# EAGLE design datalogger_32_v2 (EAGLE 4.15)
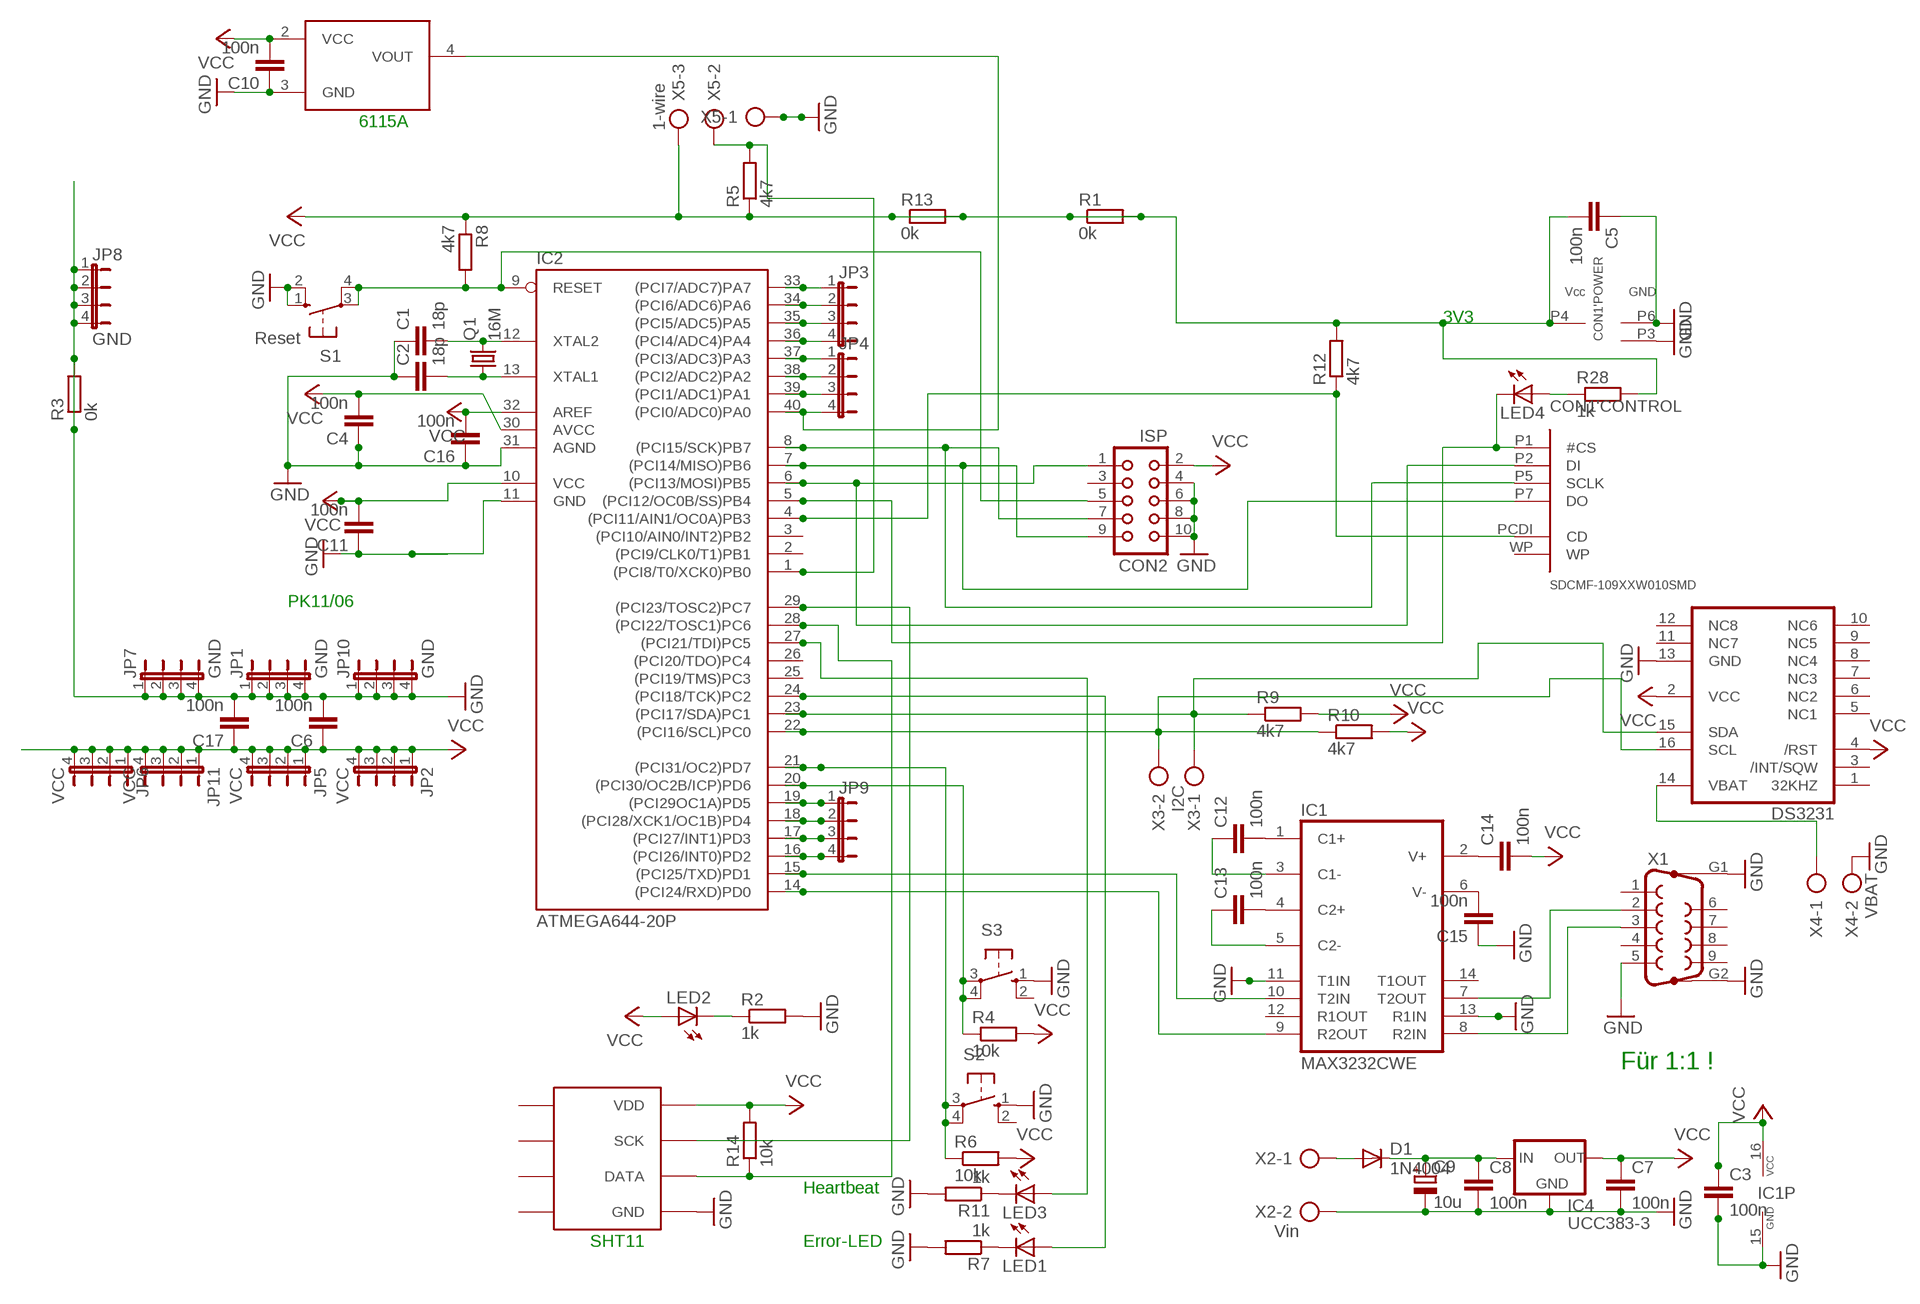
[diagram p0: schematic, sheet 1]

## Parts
C1  18p  C-EUC1206  [C1206]
C2  18p  C-EUC1206  [C1206]
C3  100n  C-EUC1206  [C1206]
C4  100n  C-EUC1206  [C1206]
C5  100n  C-EUC1206  [C1206]
C6  100n  C-EUC1206  [C1206]
C7  100n  C-EUC1206  [C1206]
C8  100n  C-EUC1206  [C1206]
C9  10u  CPOL-EU153CLV-0505  [153CLV-0505]
C10  100n  C-EUC1206  [C1206]
C11  100n  C-EUC1206  [C1206]
C12  100n  C-EUC1206  [C1206]
C13  100n  C-EUC1206  [C1206]
C14  100n  C-EUC1206  [C1206]
C15  100n  C-EUC1206  [C1206]
C16  100n  C-EUC1206  [C1206]
C17  100n  C-EUC1206  [C1206]
CON1  SDCMF-109XXW010SMD  [SDCMF-109XXW010]
CON2  ISP  CON10  [CON10]
D1  1N4004  [DO41-10]
DS3231  DS3231  [SO16L]
IC1  MAX3232CWE  [SO16L]
IC2  ATMEGA644-20P  [DIL40]
IC4  UCC383-3  78XXS  [78XXS]
JP1  GND  JP4E  [JP4]
JP2  VCC  JP4E  [JP4]
JP3  JP4E  [JP4]
JP4  JP4E  [JP4]
JP5  VCC  JP4E  [JP4]
JP6  VCC  JP4E  [JP4]
JP7  GND  JP4E  [JP4]
JP8  GND  JP4E  [JP4]
JP9  JP4E  [JP4]
JP10  GND  JP4E  [JP4]
JP11  VCC  JP4E  [JP4]
LED1  LEDSMT1206  [1206]
LED2  LEDSMT1206  [1206]
LED3  LEDSMT1206  [1206]
LED4  LEDSMT1206  [1206]
Q1  16M  CRYTALHC49U-V  [HC49U-V]
R1  0k  R-EU_R1206  [R1206]
R2  1k  R-EU_R1206  [R1206]
R3  0k  R-EU_R1206  [R1206]
R4  10k  R-EU_M1206  [M1206]
R5  4k7  R-EU_R1206  [R1206]
R6  10k  R-EU_M1206  [M1206]
R7  1k  R-EU_R1206  [R1206]
R8  4k7  R-EU_R1206  [R1206]
R9  4k7  R-EU_M1206  [M1206]
R10  4k7  R-EU_R1206  [R1206]
R11  1k  R-EU_R1206  [R1206]
R12  4k7  R-EU_R1206  [R1206]
R13  0k  R-EU_R1206  [R1206]
R14  10k  R-EU_R1206  [R1206]
R28  1k  R-EU_R1206  [R1206]
S1  Reset  10-XX  [B3F-10XX]
S2  10-XX  [B3F-10XX]
S3  10-XX  [B3F-10XX]
SHT1  SHT11  [SHT11]
U$1  MPXHZ6115A  [SO08W]
X1  F09HP  [F09HP]
X2  Vin  AK500/2  [AK500/2]
X3  I2C  AK500/2  [AK500/2]
X4  VBAT  AK500/2  [AK500/2]
X5  1-wire  AK500/3  [AK500/3]

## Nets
GND: C1.1 C2.1 C3.2 C4.1 C5.1 C6.2 C7.2 C8.2 C9.- C10.1 C11.1 C15.1 C16.1 C17.2 CON1.P3('POWER:GND) CON1.P6('POWER:GND) CON2.4 CON2.6 CON2.8 CON2.10 DS3231.13(GND) IC1.11(T1IN) IC1.13(R1IN) IC1.15(GND) IC2.11(GND) IC2.31(AGND) IC4.GND JP1.1 JP1.2 JP1.3 JP1.4 JP7.1 JP7.2 JP7.3 JP7.4 JP8.1 JP8.2 JP8.3 JP8.4 JP10.1 JP10.2 JP10.3 JP10.4 R2.2 R3.1 R3.2 R7.2 R11.2 S1.1(S) S1.2(S1) S2.1(S) S3.1(S) SHT1.GND U$1.3(GND) X1.5 X1.G1 X1.G2 X2.2 X4.2 X5.1
N$1: C1.2 IC2.12(XTAL2) Q1.2
N$2: C2.2 IC2.13(XTAL1) Q1.1
N$3: CON1.P1('CONTROL:#CS) IC2.5((PCI12/OC0B/SS)PB4) LED4.C
N$4: CON1.P2('CONTROL:DI) CON2.1 IC2.6((PCI13/MOSI)PB5)
N$5: IC2.17((PCI27/INT1)PD3) JP9.3
N$6: IC1.10(T2IN) IC2.15((PCI25/TXD)PD1)
N$7: IC2.18((PCI28/XCK1/OC1B)PD4) JP9.2
N$8: IC2.16((PCI26/INT0)PD2) JP9.4
N$9: CON1.P7('CONTROL:DO) CON2.9 IC2.7((PCI14/MISO)PB6)
N$10: IC2.19((PCI29OC1A)PD5) JP9.1
N$11: IC2.40((PCI0/ADC0)PA0) JP4.4 U$1.4(VOUT)
N$12: IC2.39((PCI1/ADC1)PA1) JP4.3
N$13: IC2.38((PCI2/ADC2)PA2) JP4.2
N$14: IC2.37((PCI3/ADC3)PA3) JP4.1
N$15: DS3231.15(SDA) IC2.23((PCI17/SDA)PC1) R9.1 X3.1
N$17: C8.1 C9.+ D1.C IC4.IN
N$18: IC1.9(R2OUT) IC2.14((PCI24/RXD)PD0)
N$19: IC2.33((PCI7/ADC7)PA7) JP3.1
N$20: LED2.C R2.1
N$24: DS3231.14(VBAT) X4.1
N$25: D1.A X2.1
N$27: IC2.20((PCI30/OC2B/ICP)PD6) R4.1 S3.3(P) S3.4(P1)
N$28: IC2.21((PCI31/OC2)PD7) R6.1 S2.3(P) S2.4(P1)
N$29: CON1.P5('CONTROL:SCLK) CON2.7 IC2.8((PCI15/SCK)PB7)
N$30: LED1.C R7.1
N$31: DS3231.16(SCL) IC2.22((PCI16/SCL)PC0) R10.1 X3.2
N$32: IC1.8(R2IN) X1.3
N$33: IC1.7(T2OUT) X1.2
N$34: IC2.29((PCI23/TOSC2)PC7) SHT1.SCK
N$35: C12.2 IC1.1(C1+)
N$36: C13.2 IC1.4(C2+)
N$37: LED3.C R11.1
N$39: C14.1 IC1.2(V+)
N$40: IC2.34((PCI6/ADC6)PA6) JP3.2
N$41: IC2.35((PCI5/ADC5)PA5) JP3.3
N$42: IC2.36((PCI4/ADC4)PA4) JP3.4
N$43: C15.2 IC1.6(V-)
N$44: IC2.28((PCI22/TOSC1)PC6) R14.1 SHT1.DATA
N$45: LED4.A R28.1
N$46: CON1.PCDI('CONTROL:CD) IC2.4((PCI11/AIN1/OC0A)PB3) R12.1
N$49: IC2.1((PCI8/T0/XCK0)PB0) R5.2 X5.2
N$52: C12.1 IC1.3(C1-)
N$53: CON2.5 IC2.9(RESET) R8.2 S1.3(P) S1.4(P1)
N$54: C13.1 IC1.5(C2-)
PB0: IC2.24((PCI18/TCK)PC2) LED1.A
PB1: IC2.27((PCI21/TDI)PC5) LED3.A
VCC: C3.1 C4.2 C5.2 C6.1 C7.1 C10.2 C11.2 C14.2 C16.2 C17.1 CON1.P4('POWER:VCC) CON2.2 DS3231.2(VCC) DS3231.4(/RST) IC1.16(VCC) IC2.10(VCC) IC2.30(AVCC) IC2.32(AREF) IC4.OUT JP2.1 JP2.2 JP2.3 JP2.4 JP5.1 JP5.2 JP5.3 JP5.4 JP6.1 JP6.2 JP6.3 JP6.4 JP11.1 JP11.2 JP11.3 JP11.4 LED2.A R1.1 R1.2 R4.2 R5.1 R6.2 R8.1 R9.2 R10.2 R12.2 R13.1 R13.2 R14.2 R28.2 SHT1.VDD U$1.2(VCC) X5.3
Unconnected: CON1.WP('CONTROL:WP) CON2.3 DS3231.1(32KHZ) DS3231.3(/INT/SQW) DS3231.5(NC1) DS3231.6(NC2) DS3231.7(NC3) DS3231.8(NC4) DS3231.9(NC5) DS3231.10(NC6) DS3231.11(NC7) DS3231.12(NC8) IC1.12(R1OUT) IC1.14(T1OUT) IC2.2((PCI9/CLK0/T1)PB1) IC2.3((PCI10/AIN0/INT2)PB2) IC2.25((PCI19/TMS)PC3) IC2.26((PCI20/TDO)PC4) S2.2(S1) S3.2(S1) SHT1.5 SHT1.6 SHT1.7 SHT1.8 X1.1 X1.4 X1.6 X1.7 X1.8 X1.9

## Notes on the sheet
- 6115A
- 3V3
- PK11/06
- Für 1:1 !
- Heartbeat
- SHT11 | Error-LED

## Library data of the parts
C1-C8 C10-C17 = rcl:C-EU: CAPACITOR, European symbol
C9 = rcl:CPOL-EU: POLARIZED CAPACITOR, European symbol
CON1 = card_adapters:SDCMF-109XXW010: KingFont SD-CARD SDCMF-109XXW010 SPI -MODE
CON2 = con-harting:CON10: CONNECTOR
D1 = diode:1N4004: DIODE
DS3231 = maxim-7a:DS3231
IC1 = maxim:MAX3232*: True RS-232 Transceivers 3.0V to 5.5V, Low-Power up to 1Mbps, Using Four 0.1µF External Capacitors Source: http://pdfserv.maxim-ic.com/en/ds/MAX3222-MAX3241.pdf
IC2 = avr:ATMEGA644*P: MICROCONTROLLER 64 kBytes FLASH 4 kBytes SRAM 2 kBytes EEPROM DUAL USART 8-channel 10 bit ADC
IC4 = v-reg:78XXS: VOLTAGE REGULATOR
JP1-JP11 = jumper:JP4E: JUMPER
LED1-LED4 = led:LED: LED
Q1 = crystal:CRYTAL: CRYSTAL
R1-R14 R28 = rcl:R-EU_: RESISTOR, European symbol
S1-S3 = switch-omron:10-XX: OMRON SWITCH
SHT1 = sht11:SHT11
U$1 = !!!Pete:MPXHZ6115A
X1 = con-subd:F09HP: SUB-D
X2-X4 = con-ptr500:AK500/2: CONNECTOR
X5 = con-ptr500:AK500/3: CONNECTOR

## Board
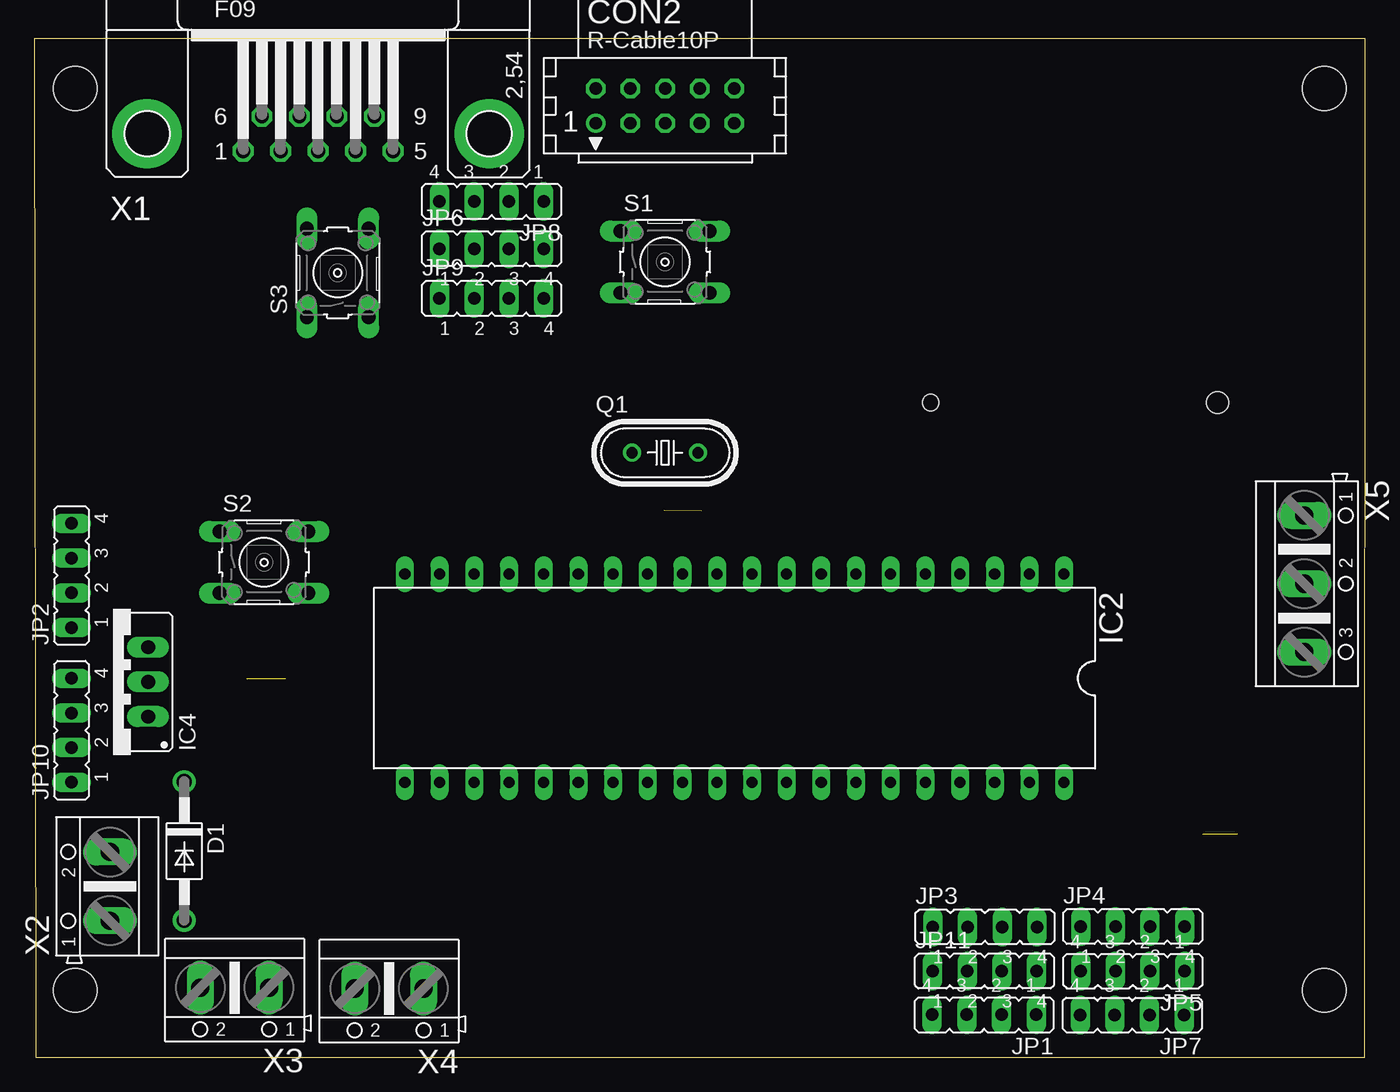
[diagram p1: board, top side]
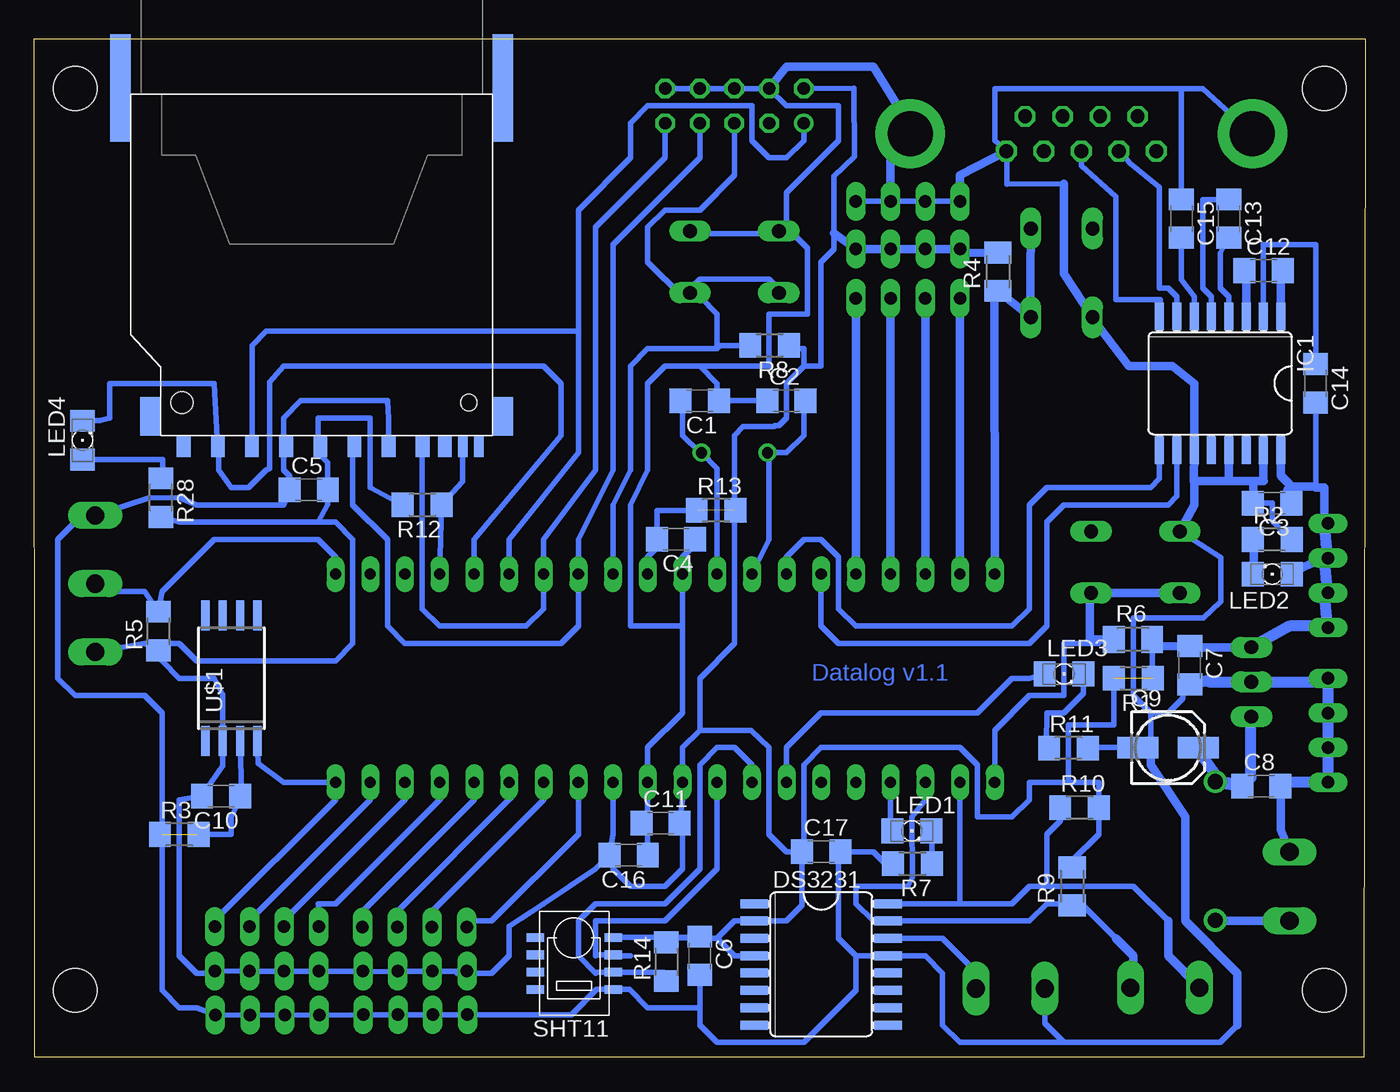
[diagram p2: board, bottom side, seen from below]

Size 97.46 x 74.59 mm. Coordinates in mm from the lower left corner, seen from the top.
Outline: 0.1,0 97.42,0 97.46,74.59 0,74.59 0.1,0
Copper layers (1*16): Top 0.035mm / dielectric 1.5mm / Bottom 0.035mm
Design rules "default": minimum track width 10mil, minimum drill 24mil, track to track 11mil, track to pad 11mil, pad to pad 11mil, via to via 11mil, smd to smd 11mil, copper to edge 40mil, drill to drill 8mil, minimum pad ring 10mil, minimum via ring 8mil, stop-mask expansion 4mil, vias tented up to drill 0mil, thermal gap 10mil
Holes 3.2 mm at 3.01,70.95 3.01,4.91 94.45,4.91 94.45,70.95

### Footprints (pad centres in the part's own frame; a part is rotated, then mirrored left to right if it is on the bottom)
C1206 = smd 1.6 x 1.8: 1 -1.4,0; 2 1.4,0
153CLV-0505 = smd 3 x 1.6: + 2.2,0; - -2.2,0
SDCMF-109XXW010 = smd 1.5 x 2.8: F1 -14,-1.4; F2 11.8,-1.4; F3 -14,-25.44; F4 14,-25.44; F5 -14,-22.9; F6 14,-22.9; F7 -14,-27.98; F8 14,-27.98 | smd 1 x 1.5: P1 6.875,0.85; P2 4.375,0.85; P3 1.875,0.85; P4 -0.625,0.85; P5 -3.125,0.85; P6 -5.625,0.85; P7 -8.125,0.85; P8 -9.75,0.85; P9 9.375,0.85 | smd 0.7 x 1.5: PCDI -11.05,0.85; WP -12.25,0.85 | hole 1.6: 9.5,-2.4 | hole 1.2: -11.5,-2.4
CON10 = drill 0.914 round: 1 -5.08,-1.27 | drill 0.914 octagon: 2 -5.08,1.27; 3 -2.54,-1.27; 4 -2.54,1.27; 5 0,-1.27; 6 0,1.27; 7 2.54,-1.27; 8 2.54,1.27; 9 5.08,-1.27; 10 5.08,1.27
DO41-10 = drill 1.118 round: A 5.08,0; C -5.08,0
SO16L = smd 0.66 x 2.032: 1 -4.445,-4.902; 2 -3.175,-4.902; 3 -1.905,-4.902; 4 -0.635,-4.902; 5 0.635,-4.902; 6 1.905,-4.902; 7 3.175,-4.902; 8 4.445,-4.902; 9 4.445,4.902; 10 3.175,4.902; 11 1.905,4.902; 12 0.635,4.902; 13 -0.635,4.902; 14 -1.905,4.902; 15 -3.175,4.902; 16 -4.445,4.902
DIL40 = drill 0.813 long: 1 -24.13,-7.62; 2 -21.59,-7.62; 3 -19.05,-7.62; 4 -16.51,-7.62; 5 -13.97,-7.62; 6 -11.43,-7.62; 7 -8.89,-7.62; 8 -6.35,-7.62; 9 -3.81,-7.62; 10 -1.27,-7.62; 11 1.27,-7.62; 12 3.81,-7.62; 13 6.35,-7.62; 14 8.89,-7.62; 15 11.43,-7.62; 16 13.97,-7.62; 17 16.51,-7.62; 18 19.05,-7.62; 19 21.59,-7.62; 20 24.13,-7.62; 21 24.13,7.62; 22 21.59,7.62; 23 19.05,7.62; 24 16.51,7.62; 25 13.97,7.62; 26 11.43,7.62; 27 8.89,7.62; 28 6.35,7.62; 29 3.81,7.62; 30 1.27,7.62; 31 -1.27,7.62; 32 -3.81,7.62; 33 -6.35,7.62; 34 -8.89,7.62; 35 -11.43,7.62; 36 -13.97,7.62; 37 -16.51,7.62; 38 -19.05,7.62; 39 -21.59,7.62; 40 -24.13,7.62
78XXS = drill 1.016 long: GND 0,-2.54; IN -2.54,-2.54; OUT 2.54,-2.54
JP4 = drill 0.914 long: 1 -3.81,0; 2 -1.27,0; 3 1.27,0; 4 3.81,0
1206 = smd 1.6 x 1.803: A -1.422,0; C 1.422,0
HC49U-V = drill 0.813 round: 1 -2.413,0; 2 2.413,0
R1206 = smd 1.6 x 1.803: 1 -1.422,0; 2 1.422,0
M1206 = smd 1.6 x 2: 1 -1.4,0; 2 1.4,0
B3F-10XX = drill 1.016 long: 1 -3.251,2.261; 2 3.251,2.261; 3 -3.251,-2.261; 4 3.251,-2.261
SHT11 = smd 1.27 x 0.635: 5 7.31,2.54; 6 7.31,3.81; 7 7.31,5.08; 8 7.31,6.35; DATA 1.59,5.08; GND 1.59,6.35; SCK 1.59,3.81; VDD 1.59,2.54
SO08W = smd 0.6 x 2.2: 1 -1.905,-4.6; 2 -0.635,-4.6; 3 0.635,-4.6; 4 1.905,-4.6; 5 1.905,4.6; 6 0.635,4.6; 7 -0.635,4.6; 8 -1.905,4.6
F09HP = drill 1.016 octagon: 1 -5.486,-1.27; 2 -2.743,-1.27; 3 0,-1.27; 4 2.743,-1.27; 5 5.486,-1.27; 6 -4.115,1.27; 7 -1.372,1.27; 8 1.372,1.27; 9 4.115,1.27 | drill 3.302 pad 5.08 round: G1 -12.522,0; G2 12.522,0
AK500/2 = drill 1.321 long: 1 -2.515,0; 2 2.515,0
AK500/3 = drill 1.321 long: 1 -5.004,0; 2 0,0; 3 5.004,0

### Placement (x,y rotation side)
C1  48.73,48.09 180 bottom
C2  42.38,48.09 0 bottom
C3  6.83,40.59 180 bottom
C4  50.47,37.96 180 bottom
C5  77.36,41.56 0 bottom
C6  48.73,7.45 270 bottom
C7  12.85,28.72 270 bottom
C8  7.62,19.86 0 bottom
C9  14.44,22.69 0 bottom
C10  83.78,19.14 180 bottom
C11  51.6,17.17 0 bottom
C12  7.46,57.62 0 bottom
C13  10,61.43 270 bottom
C14  3.64,49.36 270 bottom
C15  13.47,61.43 270 bottom
C16  53.94,14.82 180 bottom
C17  39.84,15.07 0 bottom
CON1  77.14,45.55 180 bottom
CON2  46.19,69.68 0 top
D1  10.99,15.12 270 top
DS3231  39.84,6.82 270 bottom
IC1  10.63,49.36 180 bottom
IC2  51.27,27.77 180 top
IC4  5.8,27.5 90 top
JP1  69.55,3.13 180 top
JP2  2.74,35.29 90 top
JP3  69.61,9.56 0 top
JP4  80.43,9.59 0 top
JP5  80.43,6.32 180 top
JP6  33.49,59.2 0 top
JP7  80.39,3.12 180 top
JP8  33.49,62.7 180 top
JP9  33.49,55.57 0 top
JP10  2.74,23.96 90 top
JP11  69.58,6.32 0 top
LED1  33.2,16.59 0 bottom
LED2  6.82,35.39 180 bottom
LED3  22.06,28.08 0 bottom
LED4  93.92,45.2 90 bottom
Q1  46.19,44.28 0 top
R1  16.98,27.77 180 bottom
R2  6.82,37.93 0 bottom
R3  86.83,16.34 0 bottom
R4  26.9,57.54 90 bottom
R5  88.37,31.22 90 bottom
R6  17.01,30.61 0 bottom
R7  33.16,14.2 180 bottom
R8  43.61,52.14 180 bottom
R9  21.47,12.53 90 bottom
R10  20.92,18.29 0 bottom
R11  21.73,22.66 0 bottom
R12  69.05,40.47 180 bottom
R13  47.53,40.07 0 bottom
R14  51.17,7.02 90 bottom
R28  88.17,40.99 270 bottom
S1  46.19,58.25 0 top
S2  16.83,36.26 0 top
S3  22.23,57.45 90 top
SHT1  53.47,11.33 180 bottom
U$1  83.02,27.77 0 bottom
X1  20.79,67.64 0 top
X2  5.55,12.53 90 top
X3  14.68,5.12 180 top
X4  25.99,5.05 180 top
X5  92.99,34.69 270 top

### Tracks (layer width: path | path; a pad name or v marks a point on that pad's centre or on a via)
GND  (1 unrouted)
  Bottom 0.406: CON2.4 CON2.6 | CON2.6 CON2.8 CON2.10 | CON2.4 CON2.6 | JP8.4 JP8.3 JP8.2 JP8.1 | 8.1,67.61 X1.G1 11.9,70.95 13.47,70.95 | CON2.4 42.38,69.68 40.79,69.68 38.57,69.69 38.57,67.14 42.38,63.33 42.38,60.79 42.71,60.79 42.93,60.57 | S2.1 13.67,38.6 10.57,36.6 10.57,33.4 11.87,32.2 16.97,32.2 16.97,26.51 16.98,26.5 15.71,25.23 | C3.2 6.84,40.59 6.83,40.6 6.83,39.28 5.48,37.93 R2.2 | 22.06,63.97 26.25,63.96 26.25,66.41 X1.5 26.21,66.35 27.14,67.14 27.14,70.95 13.47,70.95 | 13.47,70.95 C15.1 | C2.1 C1.1 47.46,48.09 47.46,49.36 48.73,50.63 | X4.2 23.47,2.52 22.06,1.1 | 22.06,1.1 10.63,1.1 9.36,2.37 | 37.3,7.45 37.3,7.46 DS3231.13 32.23,7.46 30.95,6.18 30.95,2.37 29.68,1.1 22.06,1.1 | 37.3,7.45 38.57,8.72 38.57,15.07 | 48.73,3.64 48.73,2.37 47.46,1.1 41.11,1.1 37.3,4.91 37.3,7.45 | 48.73,3.64 C6.2 | 48.73,3.64 52.54,3.64 53.88,4.98 SHT1.GND 56.28,4.98 58.13,3.13 JP1.4 68.31,3.14 JP1.3 JP1.2 73.43,3.14 JP1.1 76.71,3.1 JP7.4 79.13,3.1 JP7.3 81.77,3.1 JP7.2 84.29,3.08 JP7.1 85.56,3.64 86.83,3.64 88.1,4.91 88.1,16.34 | 15.71,25.23 15.71,22.69 C9.- 20.79,22.69 R11.2 | 13.37,27.24 13.37,26.3 14.44,25.23 15.71,25.23 | 79.21,44.28 79.21,43.01 78.76,42.56 C5.1 78.74,41.61 79.21,40.47 85.56,40.47 86.83,40.99 89.07,40.97 90.64,40.47 X5.1 93.18,39.2 94.45,39.2 95.72,37.93 95.72,27.77 94.45,26.5 89.37,26.5 88.1,25.23 88.1,16.34 | CON1.P6 71.52,46.75 71.59,48.09 77.94,48.09 79.21,46.82 79.21,44.28 | 79.21,44.28 79.02,44.48 CON1.P3 | 48.73,50.63 51.27,50.63 52.54,49.36 52.54,43.01 53.81,40.47 53.81,31.58 50,31.58 | 42.99,60.51 43.16,60.34 49.55,60.34 50,60.79 49.54,60.79 49.26,60.51
  Bottom 0.406: 42.99,60.51 S1.1 42.94,60.56 42.93,60.57 | 42.93,60.57 42.99,60.51 | 49.26,60.51 | 49.26,60.51 S1.2 | 48.73,50.63 43.65,50.63 43.65,54.44 40.84,54.44 40.84,59.27 40.86,59.27 42.01,60.42 42.78,60.42 42.93,60.57 | 82.26,19.11 C10.1 | 82.26,19.11 U$1.3 | 52.54,17.61 IC2.31 52.54,22.69 50,25.23 50,31.58 | 50,31.58 IC2.11 50,36.66 48.73,37.93 C4.1 | R7.2 35.16,14.2 36.03,15.07 38.57,15.07 | 38.57,15.07 C17.2 | 52.54,17.61 C11.1 | 52.54,17.61 C16.1 | 82.26,19.11 83.02,17.61 83.02,16.34 R3.2 85.56,16.34 | 88.1,16.34 R3.1
  Bottom 0.61: 7.46,42.22 IC1.15 | IC1.13 9.98,42.22 9.83,42.22 | 7.46,42.22 7.45,42.22 | 9.83,42.22 7.46,42.22 | 12.55,42.22 IC1.11 12.54,49.36 14.12,50.63 17.3,50.63 20.01,54.16 S3.1 22.08,57.4 22.08,63.43 22.06,63.97 | 12.55,42.22 9.83,42.22 | X1.5 29.68,64.6 JP8.4 29.68,62.06 | JP8.2 34.76,67.14 33.17,67.77 X1.G2 32.85,67.46 36.03,72.54 42.38,72.54 CON2.4 | X2.2 6.18,16.66 6.18,20.15 C8.2 | S2.1 12.54,40.47 12.54,42.06 12.55,42.22 | 13.37,27.24 C7.2 | 15.71,23.33 15.71,22.69 15.71,21.42 13.17,17.61 13.17,9.99 9.36,6.18 9.36,2.37 | 7.46,42.22 8.15,42.22 8.21,42.16 8.21,40.74 8.13,40.66 8.2,40.59 C3.2
  Bottom 0.813: C7.2 11.47,27.64 11.47,27.5 IC4.GND 3.07,27.5 2.77,27.8 JP10.4 2.74,25.5 3.01,25.23 JP10.3 2.74,22.96 3.01,22.69 JP10.2 2.74,20.42 3.01,20.15 JP10.1 5.92,20.15 C8.2 | C8.2 6.37,19.7 | C8.2
N$1
  Bottom 0.406: C1.2 50,48.09 50,45.55 48.73,44.28 Q1.2 47.46,43.14 IC2.12
N$2
  Bottom 0.406: IC2.13 43.65,37.93 43.65,44.15 Q1.1 42.38,44.28 41.11,45.55 41.11,48.09 C2.2
N$3
  Bottom 0.406: LED4.C 92.67,46.62 91.91,46.82 91.91,49.36 84.29,49.36 CON1.P1 83.96,44.88 83.94,43.01 83.02,41.74 81.75,41.74 80.48,43.01 80.23,43.12 80.23,49.44 79.21,50.63 60.16,50.63 58.89,49.36 58.89,45.55 65.24,37.93 IC2.5
N$4
  Bottom 0.406: CON2.1 41.11,67.14 42.38,65.87 43.65,65.87 44.92,67.14 44.92,69.68 52.54,69.68 53.81,68.41 53.81,65.87 57.62,62.06 57.62,53.17 | 57.62,53.17 57.62,44.28 62.7,37.93 IC2.6 | CON1.P2 81.52,52.13 80.48,53.17 57.62,53.17
N$5
  Bottom 0.61: IC2.17 JP9.3
N$6
  Bottom 0.406: IC1.10 13.81,41.11 14.44,40.47 22.06,40.47 23.33,39.2 23.33,31.58 24.6,30.31 38.57,30.31 39.84,31.58 IC2.15
  Bottom 0.61: IC1.10 13.81,44.6
N$7
  Bottom 0.61: IC2.18 JP9.2
N$8
  Bottom 0.61: IC2.16 JP9.4
N$9
  Bottom 0.406: CON2.9 51.27,65.87 56.35,60.79 56.35,43.01 60.16,37.93 IC2.7 60.16,32.85 61.43,31.58 67.78,31.58 69.05,32.85 69.05,44.28 69.02,44.32 CON1.P7
N$10
  Bottom 0.61: IC2.19 JP9.1
N$11
  Bottom 0.406: IC2.40 75.41,20.09 | IC2.40 75.34,20.32 | 84.24,9.94 84.29,9.99 | JP4.4 84.24,9.94 | 84.24,9.94 84.24,10.04 75.4,18.88 IC2.40 | U$1.4 81.05,21.52 79.21,20.15 IC2.40
N$12
  Bottom 0.406: 72.79,20.13 IC2.39 72.86,18.88 81.7,10.04 81.7,9.94 | 81.7,9.94 81.75,9.99 | JP4.3 81.7,9.94
N$13
  Bottom 0.406: IC2.38 70.29,20.13 70.29,18.91 79.16,10.04 79.16,9.94 | 79.16,9.94 79.21,9.99 | JP4.2 79.16,9.94
N$14
  Bottom 0.406: IC2.37 67.71,20.13 67.71,18.95 75.4,11.26 76.67,11.26 76.62,11.21 76.62,9.94 | 76.62,9.94 76.67,9.99 | JP4.1 76.62,9.94
N$15
  Bottom 0.406: 18.25,8.72 20.79,11.26 21.59,11.26 | 36.03,9.99 37.3,11.26 37.3,12.53 33.49,12.53 33.15,13.19 33.18,17.61 32.22,18.88 IC2.23 | 36.03,9.99 24.6,9.99 23.33,11.26 21.59,11.26 | 21.59,11.26 21.59,10.96 R9.1 | 36.03,9.99 DS3231.15
  Bottom 0.61: 18.25,8.72 16.98,7.45 16.98,4.91 X3.1
N$16
  Bottom 0.406: 55.08,7.45 53.81,7.45
N$17
  Bottom 0.813: 9.07,19.91 9.07,20 | C8.1 9.07,19.91 | D1.C 8.77,19.95 9.07,19.91 | C9.+ 12.27,22.66 12.27,22.57 10.46,20.03 C8.1 | 8.37,24.99 8.37,25 | 8.37,24.99 IC4.IN | C8.1 8.37,20.51 8.37,24.99
N$18
  Bottom 0.406: IC1.9 15.08,42.38 15.71,41.74 23.33,41.74 24.6,40.47 24.6,32.85 25.87,31.58 37.3,31.58 38.57,32.85 38.57,36.66 39.84,37.93 41.11,37.93 42.38,36.66 IC2.14
  Bottom 0.61: IC1.9 15.08,44.6
N$19
  Bottom 0.406: JP3.1 65.83,9.32 65.24,9.99 63.97,9.99 57.62,16.34 IC2.33
N$20
  Bottom 0.61: R2.1 8.09,37.93 LED2.C
N$24
  Bottom 0.406: X4.1 28.5,6.28 30.95,8.72 34.76,8.72 34.77,8.72 DS3231.14
N$25
  Bottom 0.61: 11.03,10 11.21,10 | 11.03,10 D1.A | X2.1 5.56,10 11.03,10
N$27
  Bottom 0.61: 27.46,35.39 IC2.20 27.17,56.2 R4.1 26.97,56.2 S3.3 24.57,53.7 S3.4
N$28
  Bottom 0.406: IC2.21 27.14,23.96 24.6,26.5 24.6,26.51 22.06,26.5 22.06,30.31 19.52,30.31 19.52,30.62
  Bottom 0.61: S2.3 S2.4 20.15,34.12 20.15,30.63 19.52,30.62 R6.1
N$29
  Bottom 0.406: CON2.7 48.73,65.87 55.08,59.52 55.08,43.01 57.62,37.93 | 57.62,37.93 IC2.8 | 57.62,37.93 57.62,31.58 58.89,30.31 70.32,30.31 71.59,31.58 71.59,37.93 74.13,40.47 74.13,44.94 CON1.P5 74.02,44.4 74.13,44.28
N$30
  Bottom 0.406: LED1.C 31.75,16.68 R7.1
N$31
  Bottom 0.406: 14.44,9.99 16.98,12.53 23.33,12.53 | 23.33,12.53 24.6,12.53 25.87,11.26 29.68,11.26 | DS3231.16 33.49,11.26 29.68,11.26 | R10.1 22.34,17.33 23.33,16.34 23.33,12.53 | 29.68,11.26 IC2.22
  Bottom 0.61: 12.11,5.12 11.9,4.91 | X3.2 12.11,5.12 | 14.44,9.99 14.44,7.45 12.11,5.12
N$32
  Bottom 0.406: IC1.8 15.02,55.48 18.27,55.48 18.25,63.02 20.79,65.3 X1.3 20.79,66.5
N$33
  Bottom 0.406: IC1.7 13.81,55.71 14.44,56.34 15.08,56.34 15.08,63.73 17.25,65.5 18.05,66.5 X1.2
N$34
  Bottom 0.406: SHT1.SCK 56.28,7.52 56.35,7.45 56.35,9.99 51.27,9.99 47.46,13.8 IC2.29
N$35
  Bottom 0.61: C12.2 6.18,56.98 IC1.1
N$36
  Bottom 0.406: IC1.4 10,55.71 10.63,56.34 10.63,58.88 10,60.16 C13.2
  Bottom 0.61: C13.2 10,59.52
N$37
  Bottom 0.406: R11.1 23.34,23.08 23.33,25.23 22.06,25.23 20.79,26.5 20.66,26.66 LED3.C
N$39
  Bottom 0.406: C14.1 3.64,59.52 7.46,59.52 IC1.2 7.46,53.8
N$40
  Bottom 0.406: IC2.34 60.16,18.88 68.34,10.7 68.34,9.97 68.33,9.32 JP3.2 68.34,9.42 68.29,9.47
N$41
  Bottom 0.406: IC2.35 62.51,20.33 62.51,19.07 70.83,10.75 70.83,9.7 | JP3.3 70.94,9.51 | JP3.3 70.88,9.65 70.83,9.7 | JP3.3 70.85,9.6 | 70.83,9.7 70.87,9.74
N$42
  Bottom 0.406: IC2.36 65.24,18.88 73.42,10.7 73.42,9.54 | 73.42,9.54 73.44,9.52 | JP3.4 73.42,9.54 | 73.42,9.54 JP3.4
N$43
  Bottom 0.406: IC1.6 12.54,55.71 13.47,56.96 C15.2 13.47,60.17
N$44
  Bottom 0.406: R14.1 51.27,6.18 51.34,6.25 SHT1.DATA 56.28,6.25 56.35,6.18 57.62,7.45 57.62,9.99 56.35,11.26 51.27,11.26 48.73,13.8 48.73,21.42 47.46,22.69 46.19,22.69 44.92,21.42 IC2.28
N$45
  Bottom 0.406: LED4.A 88.05,43.79 88.07,42.34 R28.1
N$46
  Bottom 0.406: CON1.PCDI 66.09,42.16 66.51,41.74 R12.1 IC2.4
N$49
  Bottom 0.406: 92.82,34.8 X5.2 92.73,34.41 93.18,35.39 93.18,34.12 89.37,34.12 R5.2 88.1,34.12 84.29,37.93 76.67,37.93 75.4,36.66 IC2.1
N$52
  Bottom 0.61: C12.1 8.73,56.98 IC1.3
N$53
  Bottom 0.406: 47.46,51.9 52.54,51.9 53.81,50.63 53.81,43.01 55.08,40.47 IC2.9 | R8.2 47.22,52.14 47.46,51.9 | 42.98,55.99 43.22,56.23 | 42.98,55.99 S1.3 | 42.98,55.99 42.7,55.71 42.38,55.71 43.65,56.98 48.73,56.98 50,55.71 | 49.44,56.05 49.32,56.17 | 49.44,56.05 S1.4 | 50,55.71 49.78,55.71 49.44,56.05 | 47.46,51.9 47.46,54.44 48.73,55.71 50,55.71 | CON2.5 46.19,64.6 48.73,62.06 51.27,62.06 52.54,60.79 52.54,58.25 50,55.71
N$54
  Bottom 0.406: IC1.5 11.27,55.71 11.9,56.34 11.9,60.16 11.91,62.83 C13.1
PB0
  Bottom 0.406: LED1.A 34.76,16.59 IC2.24
PB1
  Bottom 0.406: LED3.A 24.6,27.77 25.87,27.77 28.41,25.23 39.84,25.23 42.38,22.69 IC2.27
VCC  (2 unrouted)
  Bottom 0.406: 3.63,41.74 3.63,41.82 C14.2 | 41.43,70.95 37.44,70.98 37.42,65.97 38.89,64.53 38.89,60.36 38.89,59.2 39.84,58.25 39.84,50.63 41.11,50.63 | R6.2 15.63,30.76 R1.1 | R9.2 21.47,14.39 19.52,16.34 19.52,18.88 | R1.2 18.42,24.35 21.76,24.34 21.73,20.18 21.73,20.15 | 19.52,18.11 19.5,18.13 R10.2 19.56,18.07 | 19.52,18.11 19.52,18.88 | 19.52,18.88 19.52,20.15 21.73,20.15 | 19.56,18.07 19.52,18.11 | 19.56,18.07 19.62,18.01 | C17.1 41.24,11.13 42.38,9.99 44.92,9.99 44.91,9.99 DS3231.2 46.19,9.99 47.46,8.72 | 48.73,8.72 48.71,8.74 SHT1.VDD | 47.46,8.72 48.73,8.72 | DS3231.4 46.19,7.46 46.19,7.45 47.46,8.72 | R14.2 51.27,8.72 51.34,8.79 SHT1.VDD | 48.73,8.72 C6.1 | SHT1.VDD 48.8,8.79 48.73,8.72 | C17.1 41.11,15.07 41.11,21.42 39.84,22.69 29.68,22.69 28.41,21.42 28.41,17.61 25.87,17.61 24.6,18.88 24.6,20.15 21.73,20.15 | C17.1 42.38,15.07 43.65,16.34 43.65,22.69 44.97,23.95 48.73,23.96 | 12.98,30.12 13.17,30.31 | 12.98,30.12 C7.1 | 12.9,30.04 12.98,30.12 | 76.67,44.28 76.52,44.44 CON1.P4 76.67,44.28 | C5.2 75.96,43.57 76.67,44.28 | 41.11,50.63 42.38,49.36 42.38,46.82 42.93,46.27 43.21,46.27 43.29,46.19 45.55,46.19 46.19,45.55 46.19,39.2 | 41.11,50.63 41.11,51.9 42.38,51.9 42.19,52.09 R8.1 | X5.3 89.37,30.31 88.3,29.86 R5.1 88.32,29.6 88.1,30.31 | 83.64,23.42 U$1.2 | 83.64,23.42 83.64,21.35 C10.2 86.83,18.88 86.83,7.45 85.56,6.18 84.29,6.18 JP5.1 84.29,6.34 JP5.2 81.85,6.3 JP5.3 79.19,6.3 JP5.4 73.27,6.3 JP11.4 73.43,6.26 JP11.3 70.91,6.3 JP11.2 68.39,6.3 JP11.1 66.37,6.32 66.51,6.18 63.97,6.18 62.7,7.45 62.7,9.6 60.16,11.26 56.35,13.8 55.08,15.07 | C5.2 75.7,41.72 | R12.2 72.86,41.74 72.86,46.82 76.67,46.82 76.67,44.28
  Bottom 0.406: 83.64,23.42 83.64,26.59 84.29,27.77 86.83,27.77 88.1,29.04 88.1,30.31 | R28.2 86.83,39.2 76.67,39.2 | 76.67,39.2 75.99,40.49 76.02,41.63 C5.2 | 48.73,23.96 48.73,27.77 46.19,30.31 46.19,39.2 | 48.73,23.96 50,22.69 IC2.30 50,18.88 C11.2 50,17.27 50,13.8 51.27,12.53 53.81,12.53 55.08,13.8 55.08,15.07 | IC2.10 52.54,36.66 51.27,37.93 C4.2 51.87,40.05 48.84,40.05 R13.1 | IC2.32 55.08,16.34 C16.2 55.08,15.07 | 88.1,30.31 86.83,30.31 85.56,29.04 75.4,29.04 74.13,30.31 74.13,37.93 75.4,39.2 76.67,39.2 | 19.56,18.07 19.52,18.88 | R13.2 46.15,40.17 46.19,39.2
  Bottom 0.61: LED2.A 5.55,35.39 3.01,36.66 | 3.01,39.2 3.01,41.74 3.63,41.74 | 6.18,44.91 IC1.16 6.18,42.59 5.57,41.98 5.57,41.56 | 38.89,60.36 JP6.4 JP6.3 JP6.2 JP6.1 29.77,58.9 R4.2 | 41.43,70.95 CON2.2 | 15.71,30.31 R6.2 15.67,30.7 15.57,30.1 C7.1 | C3.1 5.43,40.44 5.47,40.4 5.57,40.5 5.57,41.56 | 5.57,41.56 5.73,41.56 5.47,41.82 3.63,41.82 | IC4.OUT 12.9,30.04
  Bottom 0.813: IC4.OUT 5.55,31.58 3.01,31.58 JP2.1 3.01,34.12 JP2.2 3.01,36.66 JP2.3 3.01,39.2 JP2.4

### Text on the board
Bottom: Datalog v1.1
